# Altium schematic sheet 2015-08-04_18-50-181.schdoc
size 367 x 134 mm; SheetNumber: 1; SheetTotal: 1
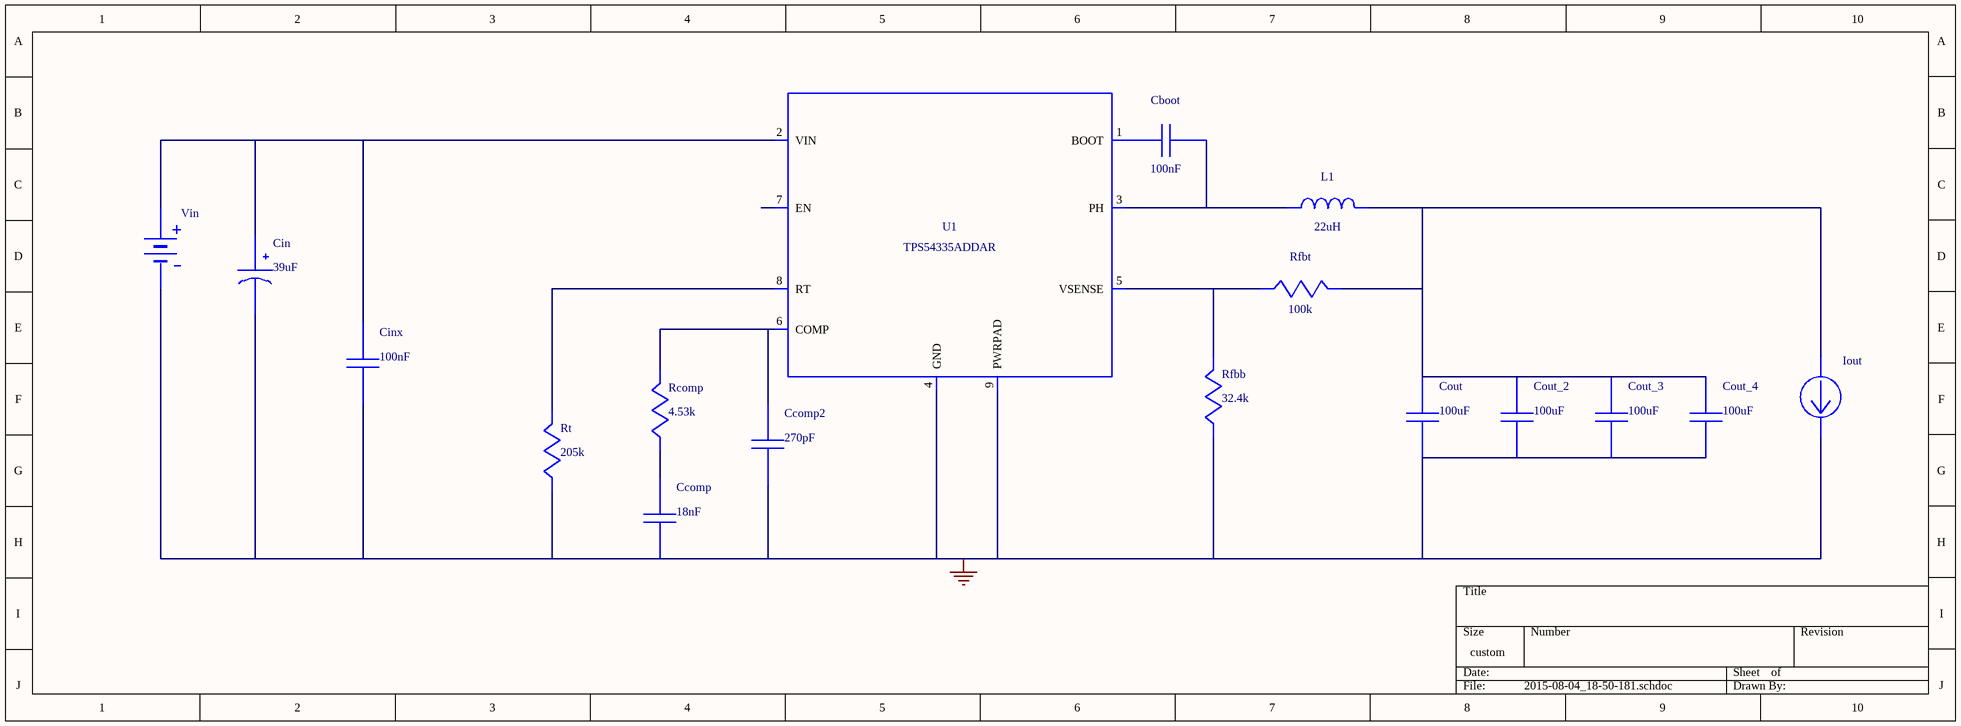
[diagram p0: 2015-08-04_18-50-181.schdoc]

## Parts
Cboot  value 100nF  (hidden comment: C0805C104K5RACTU)
Ccomp  value 18nF  (hidden comment: CC0805KRX7R9BB183)
Ccomp2  value 270pF  (hidden comment: C2012C0G1H271J)
Cin  value 39uF  (hidden comment: 35SVPF39M)
Cinx  value 100nF  (hidden comment: C0805C104K5RACTU)
Cout  value 100uF  (hidden comment: GRM31CR60J107ME39L)
Cout_2  value 100uF  (hidden comment: GRM31CR60J107ME39L)
Cout_3  value 100uF  (hidden comment: GRM31CR60J107ME39L)
Cout_4  value 100uF  (hidden comment: GRM31CR60J107ME39L)
Iout  WB_CURRENT_LOAD  (value not drawn)
L1  value 22uH  (hidden comment: SER2915L-223KL)
Rcomp  value 4.53k  (hidden comment: ERJ-6ENF4531V)
Rfbb  value 32.4k  (hidden comment: ERJ-6ENF3242V)
Rfbt  value 100k  (hidden comment: ERJ-6ENF1003V)
Rt  value 205k  (hidden comment: ERJ-6ENF2053V)
U1  TPS54335ADDAR
Vin  WB_BATTERY  (value not drawn)

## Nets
0: Ccomp.2 Ccomp2.2 Cin.2(-) Cinx.2 Cout.2 Cout_2.2 Cout_3.2 Cout_4.2 Iout.2(-) Rfbb.2 Rt.2 U1.4(GND) U1.9(PWRPAD) Vin.2(-)
NetCboot_1: Cboot.1 U1.1(BOOT)
NetCboot_2: Cboot.2 L1.1 U1.3(PH)
NetCcomp2_1: Ccomp2.1 Rcomp.1 U1.6(COMP)
NetCcomp_1: Ccomp.1 Rcomp.2
NetCin_1: Cin.1(+) Cinx.1 U1.2(VIN) Vin.1(+)
NetCout_1: Cout.1 Cout_2.1 Cout_3.1 Cout_4.1 Iout.1(+) L1.2 Rfbt.1
NetRfbb_1: Rfbb.1 Rfbt.2 U1.5(VSENSE)
NetRt_1: Rt.1 U1.8(RT)

Not connected (* = marked no-connect by the designer): U1 7(EN)

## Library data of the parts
Cboot Cinx = C0805C104K5RACTU: Manufacturer Name: Kemet
Ccomp = CC0805KRX7R9BB183: CC0805KRX7R9BB18; Manufacturer Name: Yageo America
Ccomp2 = C2012C0G1H271J: Manufacturer Name: TDK
Cin = 35SVPF39M: Manufacturer Name: Panasonic
Cout Cout_2-Cout_4 = GRM31CR60J107ME39L: GRM31CR60J107ME3; Manufacturer Name: MuRata
Iout = WB_CURRENT_LOAD: Value: UNLISTED
L1 = SER2915L-223KL: Manufacturer Name: Coilcraft
Rcomp = ERJ-6ENF4531V: Manufacturer Name: Panasonic
Rfbb = ERJ-6ENF3242V: Manufacturer Name: Panasonic
Rfbt = ERJ-6ENF1003V: Manufacturer Name: Panasonic
Rt = ERJ-6ENF2053V: Manufacturer Name: Panasonic
U1 = TPS54335ADDAR: Manufacturer Name: Texas Instruments; Value: UNLISTED
Vin = WB_BATTERY: Value: UNLISTED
